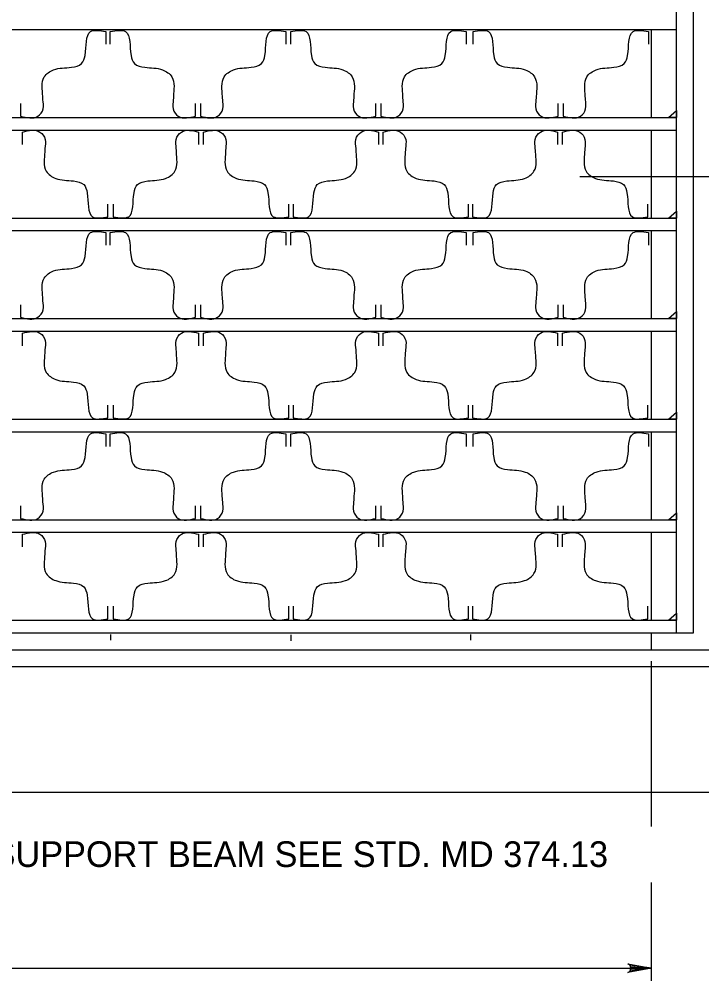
# Model space of a CAD drawing. Extents: x 0.71 to 8.05, y -5.67 to 4.31.
# Drawn here: x 5.033 to 6.63, y 0.105 to 2.355 of the extents above; entities that cross this region are included whole.
import ezdxf

# ---------------------------------------------------------------- set-up
doc = ezdxf.new("R2010")
doc.units = 0
for name, color, linetype in [('DETL-DIMS', 7, 'Continuous'), ('DETL-LINE', 7, 'Continuous'), ('DETL-NOTE', 7, 'Continuous')]:
    doc.layers.add(name, color=color, linetype=linetype)

msp = doc.modelspace()

# ---------------------------------------------------------------- linework, layer by layer
at = {"layer": 'DETL-DIMS'}
for p, q in [((6.345, 1.9865), (7.1992, 1.9865)), ((6.5122, 0.478), (6.5122, 0.8523)), ((6.5122, 0.4656), (6.5122, 0.4967)), ((6.5122, 0.1048), (6.5122, 0.3345)), ((2.7098, 0.1342), (6.5122, 0.1342))]:
    msp.add_line(p, q, dxfattribs=at)
msp.add_lwpolyline([(6.5122, 0.1342), (6.4573, 0.1239), (6.4616, 0.1268), (6.4637, 0.1305), (6.4644, 0.1342), (6.4637, 0.1379), (6.4616, 0.1416), (6.4573, 0.1445), (6.5122, 0.1342), (6.4616, 0.1416), (6.4637, 0.1379), (6.5122, 0.1342), (6.4644, 0.1342), (6.4637, 0.1305), (6.5122, 0.1342), (6.4616, 0.1268)], dxfattribs=at)
at = {"layer": 'DETL-LINE'}
for p, q in [((6.571, 0.9189), (6.571, 2.8307)), ((6.571, 0.9189), (6.571, 2.8307)), ((6.6104, 0.9189), (6.6104, 2.8307)), ((2.651, 2.3307), (6.571, 2.3307)), ((5.2358, 2.3259), (5.2358, 2.2965)), ((5.2461, 2.2965), (5.2461, 2.3259)), ((5.6565, 2.3259), (5.6565, 2.2965)), ((5.6682, 2.2965), (5.6682, 2.3259)), ((6.0785, 2.3259), (6.0785, 2.2965)), ((6.0949, 2.2965), (6.0949, 2.3259)), ((6.5052, 2.3259), (6.5052, 2.2965)), ((6.5122, 2.1248), (6.5122, 2.3307)), ((5.0363, 2.1573), (5.0363, 2.1279)), ((5.4457, 2.1279), (5.4457, 2.1573)), ((5.4569, 2.1573), (5.4569, 2.1279)), ((5.8677, 2.1279), (5.8677, 2.1573)), ((5.879, 2.1573), (5.879, 2.1279)), ((6.2944, 2.1279), (6.2944, 2.1573)), ((6.3057, 2.1573), (6.3057, 2.1279)), ((2.651, 2.1248), (6.571, 2.1248)), ((2.651, 2.0954), (6.571, 2.0954)), ((6.5122, 1.8895), (6.5122, 2.0954)), ((5.041, 2.0615), (5.041, 2.0909)), ((5.4527, 2.0909), (5.4527, 2.0615)), ((5.464, 2.0615), (5.464, 2.0909)), ((5.8734, 2.0909), (5.8734, 2.0615)), ((5.8846, 2.0615), (5.8846, 2.0909)), ((6.2929, 2.0909), (6.2929, 2.0615)), ((6.3041, 2.0615), (6.3041, 2.0909)), ((5.2406, 1.8928), (5.2406, 1.9223)), ((5.2532, 1.9223), (5.2532, 1.8928)), ((5.6635, 1.8928), (5.6635, 1.9223)), ((5.6738, 1.9223), (5.6738, 1.8928)), ((6.0842, 1.8928), (6.0842, 1.9223)), ((6.0933, 1.9223), (6.0933, 1.8928)), ((6.5037, 1.8928), (6.5037, 1.9223)), ((2.651, 1.8895), (6.571, 1.8895)), ((2.651, 1.8601), (6.571, 1.8601)), ((5.2358, 1.8554), (5.2358, 1.8259)), ((5.2461, 1.8259), (5.2461, 1.8554)), ((5.6565, 1.8554), (5.6565, 1.8259)), ((5.6682, 1.8259), (5.6682, 1.8554)), ((6.0785, 1.8554), (6.0785, 1.8259)), ((6.0949, 1.8259), (6.0949, 1.8554)), ((6.5052, 1.8554), (6.5052, 1.8259)), ((6.5122, 1.6542), (6.5122, 1.8601)), ((5.0363, 1.6867), (5.0363, 1.6573)), ((5.4457, 1.6573), (5.4457, 1.6867)), ((5.4569, 1.6867), (5.4569, 1.6573)), ((5.8677, 1.6573), (5.8677, 1.6867)), ((5.879, 1.6867), (5.879, 1.6573)), ((6.2944, 1.6573), (6.2944, 1.6867)), ((6.3057, 1.6867), (6.3057, 1.6573)), ((2.651, 1.6542), (6.571, 1.6542)), ((2.651, 1.6248), (6.571, 1.6248)), ((5.041, 1.5909), (5.041, 1.6203)), ((5.4527, 1.6203), (5.4527, 1.5909)), ((5.464, 1.5909), (5.464, 1.6203)), ((5.8734, 1.6203), (5.8734, 1.5909)), ((5.8846, 1.5909), (5.8846, 1.6203)), ((6.2929, 1.6203), (6.2929, 1.5909)), ((6.3041, 1.5909), (6.3041, 1.6203)), ((6.5122, 1.4189), (6.5122, 1.6248)), ((5.2406, 1.4222), (5.2406, 1.4517)), ((5.2532, 1.4517), (5.2532, 1.4222)), ((5.6635, 1.4222), (5.6635, 1.4517)), ((5.6738, 1.4517), (5.6738, 1.4222)), ((6.0842, 1.4222), (6.0842, 1.4517)), ((6.0933, 1.4517), (6.0933, 1.4222)), ((6.5037, 1.4222), (6.5037, 1.4517)), ((2.651, 1.4189), (6.571, 1.4189)), ((2.651, 1.3895), (6.571, 1.3895)), ((5.2358, 1.3848), (5.2358, 1.3553)), ((5.2461, 1.3553), (5.2461, 1.3848)), ((5.6565, 1.3848), (5.6565, 1.3553)), ((5.6682, 1.3553), (5.6682, 1.3848)), ((6.0785, 1.3848), (6.0785, 1.3553)), ((6.0949, 1.3553), (6.0949, 1.3848)), ((6.5052, 1.3848), (6.5052, 1.3553)), ((6.5122, 1.1836), (6.5122, 1.3895)), ((5.0363, 1.2161), (5.0363, 1.1867)), ((5.4457, 1.1867), (5.4457, 1.2161)), ((5.4569, 1.2161), (5.4569, 1.1867)), ((5.8677, 1.1867), (5.8677, 1.2161)), ((5.879, 1.2161), (5.879, 1.1867)), ((6.2944, 1.1867), (6.2944, 1.2161)), ((6.3057, 1.2161), (6.3057, 1.1867)), ((2.651, 1.1836), (6.571, 1.1836)), ((2.651, 1.1542), (6.571, 1.1542)), ((5.041, 1.1203), (5.041, 1.1497)), ((5.4527, 1.1497), (5.4527, 1.1203)), ((5.464, 1.1203), (5.464, 1.1497)), ((5.8734, 1.1497), (5.8734, 1.1203)), ((5.8846, 1.1203), (5.8846, 1.1497)), ((6.2929, 1.1497), (6.2929, 1.1203)), ((6.3041, 1.1203), (6.3041, 1.1497)), ((6.5122, 0.9483), (6.5122, 1.1542)), ((5.2406, 0.9517), (5.2406, 0.9811)), ((5.2532, 0.9811), (5.2532, 0.9517)), ((5.6635, 0.9517), (5.6635, 0.9811)), ((5.6738, 0.9811), (5.6738, 0.9517)), ((6.0842, 0.9517), (6.0842, 0.9811)), ((6.0933, 0.9811), (6.0933, 0.9517)), ((6.5037, 0.9517), (6.5037, 0.9811)), ((2.651, 0.9483), (6.571, 0.9483)), ((2.6116, 0.9189), (6.6104, 0.9189)), ((5.2473, 0.9017), (5.2473, 0.9154)), ((5.6693, 0.9003), (5.6693, 0.914)), ((6.0898, 0.9017), (6.0898, 0.9154)), ((6.5122, 0.8795), (6.5122, 0.9189)), ((2.1992, 0.8795), (7.0228, 0.8795)), ((2.1992, 0.8401), (7.0228, 0.8401)), ((2.1992, 0.546), (7.0228, 0.546))]:
    msp.add_line(p, q, dxfattribs=at)
for points in [[(6.5525, 2.1248), (6.571, 2.1412), (6.571, 2.1248)], [(6.5525, 1.8895), (6.571, 1.9059), (6.571, 1.8895)], [(6.5525, 1.6542), (6.571, 1.6706), (6.571, 1.6542)], [(6.5525, 1.4189), (6.571, 1.4353), (6.571, 1.4189)], [(6.5525, 1.1836), (6.571, 1.2), (6.571, 1.1836)], [(6.5525, 0.9483), (6.571, 0.9647), (6.571, 0.9483)]]:
    msp.add_lwpolyline(points, close=True, dxfattribs=at)
for points in [[(5.0363, 2.1279), (5.0766, 2.1279), (5.089, 2.1452), (5.0885, 2.1666), (5.0881, 2.1743), (5.0917, 2.2198), (5.1135, 2.2364), (5.1553, 2.2423), (5.1791, 2.251), (5.1873, 2.2703), (5.1999, 2.326), (5.2358, 2.3259)], [(5.0363, 2.1279), (5.0766, 2.1279), (5.089, 2.1452), (5.0885, 2.1666), (5.0881, 2.1743), (5.0917, 2.2198), (5.1135, 2.2364), (5.1553, 2.2423), (5.1791, 2.251), (5.1873, 2.2703), (5.1999, 2.326), (5.2358, 2.3259)], [(5.2461, 2.3259), (5.282, 2.326), (5.2946, 2.2703), (5.3028, 2.251), (5.3266, 2.2423), (5.3684, 2.2364), (5.3902, 2.2198), (5.3938, 2.1743), (5.3934, 2.1666), (5.3929, 2.1452), (5.4053, 2.1279), (5.4457, 2.1279)], [(5.2461, 2.3259), (5.282, 2.326), (5.2946, 2.2703), (5.3028, 2.251), (5.3266, 2.2423), (5.3684, 2.2364), (5.3902, 2.2198), (5.3938, 2.1743), (5.3934, 2.1666), (5.3929, 2.1452), (5.4053, 2.1279), (5.4457, 2.1279)], [(5.4569, 2.1279), (5.4973, 2.1279), (5.5096, 2.1452), (5.5092, 2.1666), (5.5087, 2.1743), (5.5123, 2.2198), (5.5342, 2.2364), (5.5759, 2.2423), (5.5997, 2.251), (5.6079, 2.2703), (5.6205, 2.326), (5.6565, 2.3259)], [(5.4569, 2.1279), (5.4973, 2.1279), (5.5096, 2.1452), (5.5092, 2.1666), (5.5087, 2.1743), (5.5123, 2.2198), (5.5342, 2.2364), (5.5759, 2.2423), (5.5997, 2.251), (5.6079, 2.2703), (5.6205, 2.326), (5.6565, 2.3259)], [(5.6682, 2.3259), (5.7041, 2.326), (5.7167, 2.2703), (5.7249, 2.251), (5.7487, 2.2423), (5.7905, 2.2364), (5.8123, 2.2198), (5.8159, 2.1743), (5.8154, 2.1666), (5.815, 2.1452), (5.8274, 2.1279), (5.8677, 2.1279)], [(5.6682, 2.3259), (5.7041, 2.326), (5.7167, 2.2703), (5.7249, 2.251), (5.7487, 2.2423), (5.7905, 2.2364), (5.8123, 2.2198), (5.8159, 2.1743), (5.8154, 2.1666), (5.815, 2.1452), (5.8274, 2.1279), (5.8677, 2.1279)], [(5.879, 2.1279), (5.9193, 2.1279), (5.9317, 2.1452), (5.9312, 2.1666), (5.9308, 2.1743), (5.9344, 2.2198), (5.9562, 2.2364), (5.998, 2.2423), (6.0218, 2.251), (6.03, 2.2703), (6.0426, 2.326), (6.0785, 2.3259)], [(5.879, 2.1279), (5.9193, 2.1279), (5.9317, 2.1452), (5.9312, 2.1666), (5.9308, 2.1743), (5.9344, 2.2198), (5.9562, 2.2364), (5.998, 2.2423), (6.0218, 2.251), (6.03, 2.2703), (6.0426, 2.326), (6.0785, 2.3259)], [(6.0949, 2.3259), (6.1308, 2.326), (6.1434, 2.2703), (6.1516, 2.251), (6.1754, 2.2423), (6.2172, 2.2364), (6.239, 2.2198), (6.2426, 2.1743), (6.2421, 2.1666), (6.2417, 2.1452), (6.2541, 2.1279), (6.2944, 2.1279)], [(6.0949, 2.3259), (6.1308, 2.326), (6.1434, 2.2703), (6.1516, 2.251), (6.1754, 2.2423), (6.2172, 2.2364), (6.239, 2.2198), (6.2426, 2.1743), (6.2421, 2.1666), (6.2417, 2.1452), (6.2541, 2.1279), (6.2944, 2.1279)], [(6.3057, 2.1279), (6.346, 2.1279), (6.3584, 2.1452), (6.3579, 2.1666), (6.3575, 2.1743), (6.3611, 2.2198), (6.3829, 2.2364), (6.4247, 2.2423), (6.4485, 2.251), (6.4567, 2.2703), (6.4693, 2.326), (6.5052, 2.3259)], [(6.3057, 2.1279), (6.346, 2.1279), (6.3584, 2.1452), (6.3579, 2.1666), (6.3575, 2.1743), (6.3611, 2.2198), (6.3829, 2.2364), (6.4247, 2.2423), (6.4485, 2.251), (6.4567, 2.2703), (6.4693, 2.326), (6.5052, 2.3259)], [(5.041, 2.0909), (5.0814, 2.0909), (5.0937, 2.0736), (5.0933, 2.0521), (5.0928, 2.0445), (5.0964, 1.999), (5.1183, 1.9824), (5.1601, 1.9765), (5.1839, 1.9678), (5.192, 1.9485), (5.2046, 1.8928), (5.2406, 1.8928)], [(5.2532, 1.8928), (5.2891, 1.8928), (5.3017, 1.9485), (5.3099, 1.9678), (5.3337, 1.9765), (5.3755, 1.9824), (5.3973, 1.999), (5.4009, 2.0445), (5.4005, 2.0521), (5.4, 2.0736), (5.4124, 2.0909), (5.4527, 2.0909)], [(5.464, 2.0909), (5.5043, 2.0909), (5.5167, 2.0736), (5.5162, 2.0521), (5.5158, 2.0445), (5.5194, 1.999), (5.5412, 1.9824), (5.583, 1.9765), (5.6068, 1.9678), (5.615, 1.9485), (5.6276, 1.8928), (5.6635, 1.8928)], [(5.6738, 1.8928), (5.7098, 1.8928), (5.7224, 1.9485), (5.7305, 1.9678), (5.7543, 1.9765), (5.7961, 1.9824), (5.818, 1.999), (5.8216, 2.0445), (5.8211, 2.0521), (5.8207, 2.0736), (5.833, 2.0909), (5.8734, 2.0909)], [(5.8846, 2.0909), (5.925, 2.0909), (5.9373, 2.0736), (5.9369, 2.0521), (5.9364, 2.0445), (5.94, 1.999), (5.9619, 1.9824), (6.0037, 1.9765), (6.0275, 1.9678), (6.0356, 1.9485), (6.0482, 1.8928), (6.0842, 1.8928)], [(6.0933, 1.8928), (6.1293, 1.8928), (6.1419, 1.9485), (6.15, 1.9678), (6.1738, 1.9765), (6.2156, 1.9824), (6.2375, 1.999), (6.2411, 2.0445), (6.2406, 2.0521), (6.2402, 2.0736), (6.2525, 2.0909), (6.2929, 2.0909)], [(6.3041, 2.0909), (6.3445, 2.0909), (6.3568, 2.0736), (6.3564, 2.0521), (6.356, 2.0445), (6.3595, 1.999), (6.3814, 1.9824), (6.4232, 1.9765), (6.447, 1.9678), (6.4551, 1.9485), (6.4677, 1.8928), (6.5037, 1.8928)], [(5.0363, 1.6573), (5.0766, 1.6573), (5.089, 1.6746), (5.0885, 1.696), (5.0881, 1.7037), (5.0917, 1.7492), (5.1135, 1.7658), (5.1553, 1.7717), (5.1791, 1.7804), (5.1873, 1.7997), (5.1999, 1.8554), (5.2358, 1.8554)], [(5.0363, 1.6573), (5.0766, 1.6573), (5.089, 1.6746), (5.0885, 1.696), (5.0881, 1.7037), (5.0917, 1.7492), (5.1135, 1.7658), (5.1553, 1.7717), (5.1791, 1.7804), (5.1873, 1.7997), (5.1999, 1.8554), (5.2358, 1.8554)], [(5.2461, 1.8554), (5.282, 1.8554), (5.2946, 1.7997), (5.3028, 1.7804), (5.3266, 1.7717), (5.3684, 1.7658), (5.3902, 1.7492), (5.3938, 1.7037), (5.3934, 1.696), (5.3929, 1.6746), (5.4053, 1.6573), (5.4457, 1.6573)], [(5.2461, 1.8554), (5.282, 1.8554), (5.2946, 1.7997), (5.3028, 1.7804), (5.3266, 1.7717), (5.3684, 1.7658), (5.3902, 1.7492), (5.3938, 1.7037), (5.3934, 1.696), (5.3929, 1.6746), (5.4053, 1.6573), (5.4457, 1.6573)], [(5.4569, 1.6573), (5.4973, 1.6573), (5.5096, 1.6746), (5.5092, 1.696), (5.5087, 1.7037), (5.5123, 1.7492), (5.5342, 1.7658), (5.5759, 1.7717), (5.5997, 1.7804), (5.6079, 1.7997), (5.6205, 1.8554), (5.6565, 1.8554)], [(5.4569, 1.6573), (5.4973, 1.6573), (5.5096, 1.6746), (5.5092, 1.696), (5.5087, 1.7037), (5.5123, 1.7492), (5.5342, 1.7658), (5.5759, 1.7717), (5.5997, 1.7804), (5.6079, 1.7997), (5.6205, 1.8554), (5.6565, 1.8554)], [(5.6682, 1.8554), (5.7041, 1.8554), (5.7167, 1.7997), (5.7249, 1.7804), (5.7487, 1.7717), (5.7905, 1.7658), (5.8123, 1.7492), (5.8159, 1.7037), (5.8154, 1.696), (5.815, 1.6746), (5.8274, 1.6573), (5.8677, 1.6573)], [(5.6682, 1.8554), (5.7041, 1.8554), (5.7167, 1.7997), (5.7249, 1.7804), (5.7487, 1.7717), (5.7905, 1.7658), (5.8123, 1.7492), (5.8159, 1.7037), (5.8154, 1.696), (5.815, 1.6746), (5.8274, 1.6573), (5.8677, 1.6573)], [(5.879, 1.6573), (5.9193, 1.6573), (5.9317, 1.6746), (5.9312, 1.696), (5.9308, 1.7037), (5.9344, 1.7492), (5.9562, 1.7658), (5.998, 1.7717), (6.0218, 1.7804), (6.03, 1.7997), (6.0426, 1.8554), (6.0785, 1.8554)], [(5.879, 1.6573), (5.9193, 1.6573), (5.9317, 1.6746), (5.9312, 1.696), (5.9308, 1.7037), (5.9344, 1.7492), (5.9562, 1.7658), (5.998, 1.7717), (6.0218, 1.7804), (6.03, 1.7997), (6.0426, 1.8554), (6.0785, 1.8554)], [(6.0949, 1.8554), (6.1308, 1.8554), (6.1434, 1.7997), (6.1516, 1.7804), (6.1754, 1.7717), (6.2172, 1.7658), (6.239, 1.7492), (6.2426, 1.7037), (6.2421, 1.696), (6.2417, 1.6746), (6.2541, 1.6573), (6.2944, 1.6573)], [(6.0949, 1.8554), (6.1308, 1.8554), (6.1434, 1.7997), (6.1516, 1.7804), (6.1754, 1.7717), (6.2172, 1.7658), (6.239, 1.7492), (6.2426, 1.7037), (6.2421, 1.696), (6.2417, 1.6746), (6.2541, 1.6573), (6.2944, 1.6573)], [(6.3057, 1.6573), (6.346, 1.6573), (6.3584, 1.6746), (6.3579, 1.696), (6.3575, 1.7037), (6.3611, 1.7492), (6.3829, 1.7658), (6.4247, 1.7717), (6.4485, 1.7804), (6.4567, 1.7997), (6.4693, 1.8554), (6.5052, 1.8554)], [(6.3057, 1.6573), (6.346, 1.6573), (6.3584, 1.6746), (6.3579, 1.696), (6.3575, 1.7037), (6.3611, 1.7492), (6.3829, 1.7658), (6.4247, 1.7717), (6.4485, 1.7804), (6.4567, 1.7997), (6.4693, 1.8554), (6.5052, 1.8554)], [(5.041, 1.6203), (5.0814, 1.6203), (5.0937, 1.603), (5.0933, 1.5816), (5.0928, 1.5739), (5.0964, 1.5284), (5.1183, 1.5118), (5.1601, 1.5059), (5.1839, 1.4972), (5.192, 1.4779), (5.2046, 1.4222), (5.2406, 1.4222)], [(5.2532, 1.4222), (5.2891, 1.4222), (5.3017, 1.4779), (5.3099, 1.4972), (5.3337, 1.5059), (5.3755, 1.5118), (5.3973, 1.5284), (5.4009, 1.5739), (5.4005, 1.5816), (5.4, 1.603), (5.4124, 1.6203), (5.4527, 1.6203)], [(5.464, 1.6203), (5.5043, 1.6203), (5.5167, 1.603), (5.5162, 1.5816), (5.5158, 1.5739), (5.5194, 1.5284), (5.5412, 1.5118), (5.583, 1.5059), (5.6068, 1.4972), (5.615, 1.4779), (5.6276, 1.4222), (5.6635, 1.4222)], [(5.6738, 1.4222), (5.7098, 1.4222), (5.7224, 1.4779), (5.7305, 1.4972), (5.7543, 1.5059), (5.7961, 1.5118), (5.818, 1.5284), (5.8216, 1.5739), (5.8211, 1.5816), (5.8207, 1.603), (5.833, 1.6203), (5.8734, 1.6203)], [(5.8846, 1.6203), (5.925, 1.6203), (5.9373, 1.603), (5.9369, 1.5816), (5.9364, 1.5739), (5.94, 1.5284), (5.9619, 1.5118), (6.0037, 1.5059), (6.0275, 1.4972), (6.0356, 1.4779), (6.0482, 1.4222), (6.0842, 1.4222)], [(6.0933, 1.4222), (6.1293, 1.4222), (6.1419, 1.4779), (6.15, 1.4972), (6.1738, 1.5059), (6.2156, 1.5118), (6.2375, 1.5284), (6.2411, 1.5739), (6.2406, 1.5816), (6.2402, 1.603), (6.2525, 1.6203), (6.2929, 1.6203)], [(6.3041, 1.6203), (6.3445, 1.6203), (6.3568, 1.603), (6.3564, 1.5816), (6.356, 1.5739), (6.3595, 1.5284), (6.3814, 1.5118), (6.4232, 1.5059), (6.447, 1.4972), (6.4551, 1.4779), (6.4677, 1.4222), (6.5037, 1.4222)], [(5.0363, 1.1867), (5.0766, 1.1867), (5.089, 1.204), (5.0885, 1.2255), (5.0881, 1.2331), (5.0917, 1.2786), (5.1135, 1.2952), (5.1553, 1.3011), (5.1791, 1.3098), (5.1873, 1.3291), (5.1999, 1.3848), (5.2358, 1.3848)], [(5.0363, 1.1867), (5.0766, 1.1867), (5.089, 1.204), (5.0885, 1.2255), (5.0881, 1.2331), (5.0917, 1.2786), (5.1135, 1.2952), (5.1553, 1.3011), (5.1791, 1.3098), (5.1873, 1.3291), (5.1999, 1.3848), (5.2358, 1.3848)], [(5.2461, 1.3848), (5.282, 1.3848), (5.2946, 1.3291), (5.3028, 1.3098), (5.3266, 1.3011), (5.3684, 1.2952), (5.3902, 1.2786), (5.3938, 1.2331), (5.3934, 1.2255), (5.3929, 1.204), (5.4053, 1.1867), (5.4457, 1.1867)], [(5.2461, 1.3848), (5.282, 1.3848), (5.2946, 1.3291), (5.3028, 1.3098), (5.3266, 1.3011), (5.3684, 1.2952), (5.3902, 1.2786), (5.3938, 1.2331), (5.3934, 1.2255), (5.3929, 1.204), (5.4053, 1.1867), (5.4457, 1.1867)], [(5.4569, 1.1867), (5.4973, 1.1867), (5.5096, 1.204), (5.5092, 1.2255), (5.5087, 1.2331), (5.5123, 1.2786), (5.5342, 1.2952), (5.5759, 1.3011), (5.5997, 1.3098), (5.6079, 1.3291), (5.6205, 1.3848), (5.6565, 1.3848)], [(5.4569, 1.1867), (5.4973, 1.1867), (5.5096, 1.204), (5.5092, 1.2255), (5.5087, 1.2331), (5.5123, 1.2786), (5.5342, 1.2952), (5.5759, 1.3011), (5.5997, 1.3098), (5.6079, 1.3291), (5.6205, 1.3848), (5.6565, 1.3848)], [(5.6682, 1.3848), (5.7041, 1.3848), (5.7167, 1.3291), (5.7249, 1.3098), (5.7487, 1.3011), (5.7905, 1.2952), (5.8123, 1.2786), (5.8159, 1.2331), (5.8154, 1.2255), (5.815, 1.204), (5.8274, 1.1867), (5.8677, 1.1867)], [(5.6682, 1.3848), (5.7041, 1.3848), (5.7167, 1.3291), (5.7249, 1.3098), (5.7487, 1.3011), (5.7905, 1.2952), (5.8123, 1.2786), (5.8159, 1.2331), (5.8154, 1.2255), (5.815, 1.204), (5.8274, 1.1867), (5.8677, 1.1867)], [(5.879, 1.1867), (5.9193, 1.1867), (5.9317, 1.204), (5.9312, 1.2255), (5.9308, 1.2331), (5.9344, 1.2786), (5.9562, 1.2952), (5.998, 1.3011), (6.0218, 1.3098), (6.03, 1.3291), (6.0426, 1.3848), (6.0785, 1.3848)], [(5.879, 1.1867), (5.9193, 1.1867), (5.9317, 1.204), (5.9312, 1.2255), (5.9308, 1.2331), (5.9344, 1.2786), (5.9562, 1.2952), (5.998, 1.3011), (6.0218, 1.3098), (6.03, 1.3291), (6.0426, 1.3848), (6.0785, 1.3848)], [(6.0949, 1.3848), (6.1308, 1.3848), (6.1434, 1.3291), (6.1516, 1.3098), (6.1754, 1.3011), (6.2172, 1.2952), (6.239, 1.2786), (6.2426, 1.2331), (6.2421, 1.2255), (6.2417, 1.204), (6.2541, 1.1867), (6.2944, 1.1867)], [(6.0949, 1.3848), (6.1308, 1.3848), (6.1434, 1.3291), (6.1516, 1.3098), (6.1754, 1.3011), (6.2172, 1.2952), (6.239, 1.2786), (6.2426, 1.2331), (6.2421, 1.2255), (6.2417, 1.204), (6.2541, 1.1867), (6.2944, 1.1867)], [(6.3057, 1.1867), (6.346, 1.1867), (6.3584, 1.204), (6.3579, 1.2255), (6.3575, 1.2331), (6.3611, 1.2786), (6.3829, 1.2952), (6.4247, 1.3011), (6.4485, 1.3098), (6.4567, 1.3291), (6.4693, 1.3848), (6.5052, 1.3848)], [(6.3057, 1.1867), (6.346, 1.1867), (6.3584, 1.204), (6.3579, 1.2255), (6.3575, 1.2331), (6.3611, 1.2786), (6.3829, 1.2952), (6.4247, 1.3011), (6.4485, 1.3098), (6.4567, 1.3291), (6.4693, 1.3848), (6.5052, 1.3848)], [(5.041, 1.1497), (5.0814, 1.1497), (5.0937, 1.1324), (5.0933, 1.111), (5.0928, 1.1033), (5.0964, 1.0578), (5.1183, 1.0412), (5.1601, 1.0353), (5.1839, 1.0266), (5.192, 1.0073), (5.2046, 0.9516), (5.2406, 0.9517)], [(5.2532, 0.9517), (5.2891, 0.9516), (5.3017, 1.0073), (5.3099, 1.0266), (5.3337, 1.0353), (5.3755, 1.0412), (5.3973, 1.0578), (5.4009, 1.1033), (5.4005, 1.111), (5.4, 1.1324), (5.4124, 1.1497), (5.4527, 1.1497)], [(5.464, 1.1497), (5.5043, 1.1497), (5.5167, 1.1324), (5.5162, 1.111), (5.5158, 1.1033), (5.5194, 1.0578), (5.5412, 1.0412), (5.583, 1.0353), (5.6068, 1.0266), (5.615, 1.0073), (5.6276, 0.9516), (5.6635, 0.9517)], [(5.6738, 0.9517), (5.7098, 0.9516), (5.7224, 1.0073), (5.7305, 1.0266), (5.7543, 1.0353), (5.7961, 1.0412), (5.818, 1.0578), (5.8216, 1.1033), (5.8211, 1.111), (5.8207, 1.1324), (5.833, 1.1497), (5.8734, 1.1497)], [(5.8846, 1.1497), (5.925, 1.1497), (5.9373, 1.1324), (5.9369, 1.111), (5.9364, 1.1033), (5.94, 1.0578), (5.9619, 1.0412), (6.0037, 1.0353), (6.0275, 1.0266), (6.0356, 1.0073), (6.0482, 0.9516), (6.0842, 0.9517)], [(6.0933, 0.9517), (6.1293, 0.9516), (6.1419, 1.0073), (6.15, 1.0266), (6.1738, 1.0353), (6.2156, 1.0412), (6.2375, 1.0578), (6.2411, 1.1033), (6.2406, 1.111), (6.2402, 1.1324), (6.2525, 1.1497), (6.2929, 1.1497)], [(6.3041, 1.1497), (6.3445, 1.1497), (6.3568, 1.1324), (6.3564, 1.111), (6.356, 1.1033), (6.3595, 1.0578), (6.3814, 1.0412), (6.4232, 1.0353), (6.447, 1.0266), (6.4551, 1.0073), (6.4677, 0.9516), (6.5037, 0.9517)]]:
    msp.add_spline(points, degree=3, dxfattribs=at)

# ---------------------------------------------------------------- texts
at = {"layer": 'DETL-NOTE'}
msp.add_text('SUPPORT BEAM SEE STD. MD 374.13', height=0.06, dxfattribs=at).set_placement((4.9707, 0.3711))

doc.saveas('drawing.dxf')
